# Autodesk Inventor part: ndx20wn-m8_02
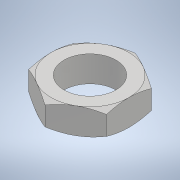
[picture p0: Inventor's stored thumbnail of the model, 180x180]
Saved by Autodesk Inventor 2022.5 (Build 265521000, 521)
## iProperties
Part Number: ndx20wn-m8_02
Material: 一般
Document SubType Name: Modeling
Designer: ImaoCorp
Density: 1 g/cm^3
Appearance: 既定
Author: ImaoCorp
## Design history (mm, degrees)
feature "ndx20wn-m8_02"
node "ソリッド1"
